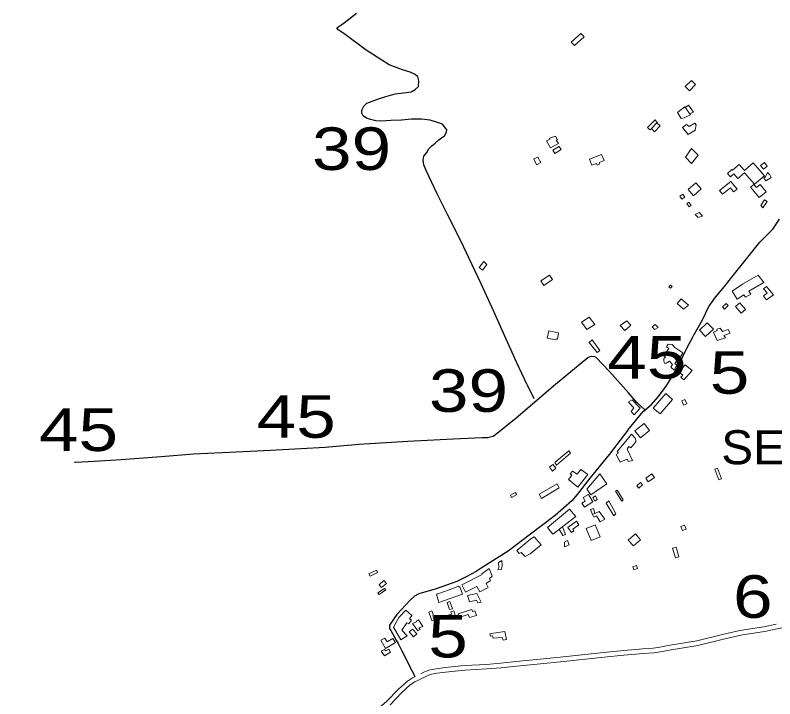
# Model space of a CAD drawing. Extents: x 476989 to 498418, y 4381813 to 4416555.
# Drawn here: x 484707 to 485600, y 4384840 to 4385643 of the extents above; entities that cross this region are included whole.
import ezdxf
from ezdxf.enums import TextEntityAlignment as Align

# ---------------------------------------------------------------- set-up
doc = ezdxf.new("R2010")
doc.units = 0
doc.header["$LTSCALE"] = 20
doc.linetypes.add('MEDIUM_DASHED', pattern=[4.5, 3, -1.5])
for name, color, linetype, lineweight in [('13', 7, 'Continuous', 13), ('36', 7, 'Continuous', 13), ('47', 7, 'Continuous', 13), ('48', 7, 'MEDIUM_DASHED', 13), ('6', 7, 'Continuous', 25)]:
    doc.layers.add(name, color=color, linetype=linetype, lineweight=lineweight)
doc.layers.add('7', color=7, linetype='Continuous')

msp = doc.modelspace()

# ---------------------------------------------------------------- linework, layer by layer
at = {"layer": '36'}
for points in [[(485422.62, 4384890.78), (485445.5, 4384892.7), (485457.67, 4384893.65), (485465.81, 4384894.8), (485475.68, 4384896.69), (485509.45, 4384902.29), (485539.74, 4384909.58), (485559.9, 4384914.32), (485587.94, 4384918.87), (485619.65, 4384925.47)], [(485422.69, 4384896.4), (485445.04, 4384898.28), (485457.06, 4384899.22), (485464.89, 4384900.34), (485474.69, 4384902.21), (485508.34, 4384907.79), (485538.44, 4384915.04), (485558.81, 4384919.82), (485586.93, 4384924.38), (485601.44, 4384927.38)], [(485147.77, 4384832.69), (485161.73, 4384847.04), (485171.53, 4384855.86), (485177.07, 4384859.62), (485182.06, 4384861.97), (485189.79, 4384866.01), (485195.1, 4384868.19), (485202.95, 4384869.58), (485213.04, 4384870.95), (485235.55, 4384873.26), (485261.75, 4384874.66), (485278.18, 4384876.14), (485300.64, 4384878.33), (485328.67, 4384881.11), (485348.27, 4384882.97), (485399.25, 4384888.59), (485422.62, 4384890.78)], [(485183.89, 4384869.09), (485187.49, 4384870.96), (485193.57, 4384873.46), (485202.11, 4384874.97), (485212.4, 4384876.37), (485235.13, 4384878.7), (485261.36, 4384880.1), (485277.67, 4384881.57), (485300.11, 4384883.76), (485328.15, 4384886.54), (485347.71, 4384888.4), (485398.68, 4384894.02), (485422.69, 4384896.4)], [(484707.31, 4384502.21), (484734.52, 4384522.99), (484765.58, 4384547.94), (484791.08, 4384567.66), (484812.71, 4384583.16), (484848.35, 4384610.12), (484888.3, 4384639.7), (484927.89, 4384667.41), (484957.41, 4384688.58), (484989.83, 4384714.56), (485027.43, 4384743.96), (485060.66, 4384769.23), (485090.09, 4384790.79), (485112.52, 4384809.73), (485128.38, 4384822.96), (485144.01, 4384836.66), (485157.94, 4384850.98), (485168.16, 4384860.16), (485174.35, 4384864.37), (485176.85, 4384865.55)]]:
    msp.add_lwpolyline(points, dxfattribs=at)
at = {"layer": '47'}
for p, q in [((485430.73, 4385278.66), (485429.6, 4385277.65)), ((485429.64, 4385279.89), (485430.73, 4385278.66)), ((485431.59, 4385150.48), (485427.01, 4385144.68))]:
    msp.add_line(p, q, dxfattribs=at)
for points in [[(485375.86, 4385617.36), (485364.42, 4385607.2), (485360.77, 4385611.28), (485372.16, 4385621.45)], [(485501.94, 4385566.31), (485494.71, 4385558.99), (485499.66, 4385554.11), (485506.89, 4385561.43)], [(485500.76, 4385525.8), (485493.57, 4385522.16), (485490.11, 4385521.53), (485485.71, 4385528.5), (485494.07, 4385535.43)], [(485461.45, 4385516.54), (485454.91, 4385509.66), (485458.68, 4385506.07), (485465.22, 4385512.95)], [(485491.39, 4385511.08), (485498.17, 4385502.8), (485506.43, 4385508.01), (485507.49, 4385514.15), (485506.17, 4385515.97), (485499.43, 4385512.02), (485496.02, 4385514.62)], [(485336.5, 4385486.96), (485331.77, 4385495.38), (485335.76, 4385497.44), (485335.29, 4385498.25), (485342.2, 4385500.73), (485344.58, 4385496.66), (485343.21, 4385496.15), (485345.76, 4385492.09)], [(485346.38, 4385488.49), (485348.86, 4385485.12), (485341.52, 4385480.52), (485338.96, 4385484.25)], [(485382.2, 4385473.84), (485385, 4385466.76), (485390.55, 4385468.79), (485391.34, 4385466.68), (485394.27, 4385468.09), (485393.65, 4385469.76), (485399.3, 4385472.35), (485396.43, 4385479.26)], [(485501.99, 4385486.17), (485494.94, 4385476.06), (485501.89, 4385468.84), (485509.91, 4385478.63)], [(485316.66, 4385474.25), (485319.79, 4385467.3), (485324.91, 4385469.72), (485321.65, 4385475.92)], [(485576.12, 4385444.28), (485564.24, 4385457.89), (485556.57, 4385451.2), (485551.89, 4385456.56), (485547.94, 4385453.11), (485544.46, 4385457.09), (485549.66, 4385461.64), (485550.29, 4385460.91), (485558.02, 4385467.59), (485564.31, 4385460.3), (485574.72, 4385469.29), (485587.69, 4385454.27)], [(485583.19, 4385466.47), (485586.58, 4385462.08), (485591.06, 4385465.53), (485587.67, 4385469.92)], [(485591.25, 4385458.17), (485589.16, 4385453.18), (485586.96, 4385451.48), (485589.53, 4385448.14), (485595.75, 4385452.26), (485594.06, 4385455.21)], [(485513.39, 4385438.88), (485504.37, 4385430.87), (485498, 4385438.05), (485507.02, 4385446.06)], [(485534.82, 4385436.85), (485548.41, 4385447.53), (485555.55, 4385438.42), (485551.49, 4385435.24), (485547.76, 4385439.99), (485538.35, 4385432.6)], [(485571.57, 4385440.75), (485581.68, 4385428.75), (485589.75, 4385435.55), (485582.63, 4385443.99), (485578.45, 4385440.47), (485575.5, 4385443.96)], [(485488.51, 4385430.38), (485490.9, 4385426.94), (485494.12, 4385429.18), (485491.73, 4385432.62)], [(485587.94, 4385426.11), (485583.51, 4385419.27), (485585.96, 4385416.4), (485590.99, 4385424.11)], [(485496.41, 4385421.49), (485499.18, 4385417.58), (485501.63, 4385419.31), (485498.86, 4385423.22)], [(485515.18, 4385406.96), (485509.98, 4385405.16), (485506.28, 4385408.67), (485511.49, 4385410.99)], [(485261.75, 4385350.07), (485256.55, 4385343.42), (485252.49, 4385346.53), (485257.99, 4385353.63)], [(485328.63, 4385325.22), (485324.86, 4385330.61), (485335.14, 4385337.31), (485338.56, 4385332.44)], [(485549.71, 4385318.83), (485561.98, 4385326.75), (485580.37, 4385337.6), (485587.23, 4385328.94), (485569.52, 4385318.84), (485571.72, 4385315.06), (485565.44, 4385311.55), (485563.46, 4385314.43), (485555.65, 4385309.29)], [(485477.4, 4385325.79), (485479.27, 4385324.15), (485477.42, 4385322.04), (485475.55, 4385323.68)], [(485590.08, 4385308.34), (485598.5, 4385314.38), (485590.16, 4385324.25), (485586.82, 4385321.45), (485590.88, 4385316.59), (485586.69, 4385312.74)], [(485498.45, 4385302.23), (485490, 4385309.55), (485485.17, 4385303.97), (485492.83, 4385297.33)], [(485542.75, 4385303.99), (485538.6, 4385300.17), (485540.85, 4385297.49), (485545.11, 4385301.63)], [(485559.04, 4385304.89), (485565.52, 4385297.05), (485560.45, 4385292.86), (485553.97, 4385300.7)], [(485379.07, 4385273.78), (485372.7, 4385282.19), (485381.81, 4385288.09), (485388.5, 4385279.35)], [(485462.96, 4385275.95), (485458.57, 4385273.46), (485455.91, 4385276.72), (485459.56, 4385279.6)], [(485520.66, 4385281.5), (485511.38, 4385272.95), (485518.48, 4385265.25), (485527.76, 4385273.8)], [(485535.88, 4385275.28), (485538.53, 4385271.26), (485545.24, 4385273.79), (485547.35, 4385269.41), (485540.18, 4385266.44), (485542.09, 4385263.63), (485532.37, 4385260.7), (485528.09, 4385270.51), (485532.09, 4385272.56), (485531.74, 4385273.91)], [(485345.88, 4385269.62), (485344.44, 4385262.34), (485343.13, 4385262.81), (485342.47, 4385261.32), (485332.59, 4385263.42), (485334.26, 4385272.11)], [(485385.42, 4385261.39), (485394.28, 4385248.91), (485391.08, 4385246.45), (485381.82, 4385258.29)], [(485491.87, 4385246.19), (485482.36, 4385252.63), (485479.41, 4385256.13), (485474.53, 4385256.42), (485472.69, 4385253.22), (485475.36, 4385251.23), (485469.68, 4385242.53), (485471.61, 4385240.93), (485470.02, 4385239.75), (485469.7, 4385238.63), (485469.68, 4385237.51), (485469.66, 4385235.93), (485469.95, 4385235.1), (485470.91, 4385233.81), (485472.33, 4385233.94), (485474.23, 4385235.19), (485476.05, 4385236.29), (485479.89, 4385232.48), (485477.67, 4385229.44), (485481.67, 4385225.85), (485484.68, 4385231.74), (485482.54, 4385233.72), (485485.91, 4385239.08), (485487.71, 4385238.75)], [(485502.9, 4385225.4), (485493.14, 4385214.36), (485489.67, 4385217.42), (485491.81, 4385219.85), (485487.35, 4385223.77), (485494.77, 4385232.21)], [(485471.75, 4385198.38), (485457.07, 4385181.29), (485465.18, 4385174.32), (485479.86, 4385191.41)], [(485494.31, 4385191.46), (485496.54, 4385186.14), (485492.79, 4385184.57), (485490.56, 4385189.89)], [(485446.33, 4385162.95), (485435.67, 4385154.43), (485442.19, 4385146.28), (485452.85, 4385154.8)], [(485341.54, 4385117.13), (485358, 4385131.01), (485359.88, 4385128.25), (485343.44, 4385114.36)], [(485335.12, 4385111.93), (485338.88, 4385107.2), (485342.55, 4385110.64), (485339.07, 4385115.06)], [(485357.51, 4385097.15), (485368.62, 4385088.17), (485380.36, 4385103.26), (485372.01, 4385109.03), (485367.56, 4385103.58), (485362.09, 4385107.01), (485359.66, 4385104.07), (485361.62, 4385102.4)], [(485379.23, 4385085.92), (485383.64, 4385079.14), (485402.54, 4385092.1), (485394.26, 4385104.11)], [(485458.4, 4385099.53), (485451.27, 4385094.65), (485448.34, 4385098.92), (485455.47, 4385103.8)], [(485532.7, 4385110.77), (485537.34, 4385098.3), (485534.08, 4385097.09), (485529.44, 4385109.56)], [(485346.7, 4385087.36), (485344.04, 4385092.2), (485323.12, 4385080.13), (485325.71, 4385075.16)], [(485444.62, 4385090.94), (485440.26, 4385087.1), (485437.78, 4385089.92), (485442.14, 4385093.76)], [(485290.74, 4385076.25), (485296.71, 4385079.76), (485295.04, 4385081.98), (485289.22, 4385078.94)], [(485376.42, 4385064.78), (485386.3, 4385071.05), (485380.99, 4385079.78), (485374.59, 4385076.18), (485377.22, 4385071.74), (485373.36, 4385069.71)], [(485386.27, 4385076.22), (485388.49, 4385071.93), (485391.18, 4385073.68), (485389.36, 4385078.3)], [(485414.69, 4385084.77), (485421.67, 4385073.34), (485420.02, 4385071.95), (485412.62, 4385083.7)], [(485401.88, 4385069.6), (485410.97, 4385054.66), (485413.3, 4385056.85), (485404.78, 4385072.14)], [(485332.83, 4385040.86), (485358.81, 4385062.46), (485366.1, 4385053.67), (485338.95, 4385033.1)], [(485400.09, 4385050.6), (485393.57, 4385059.83), (485385.55, 4385056.3), (485387.34, 4385053.1), (485390.5, 4385054.62), (485394.78, 4385047.66)], [(485356.66, 4385040.89), (485366.9, 4385048.44), (485369.63, 4385044), (485362.81, 4385039.04), (485363.91, 4385036.96), (485361.23, 4385035.02)], [(485378.19, 4385039.92), (485388.72, 4385044.18), (485394.8, 4385029.82), (485384.25, 4385025.7)], [(485489.62, 4385042.13), (485493.73, 4385043.77), (485495.65, 4385038.96), (485491.54, 4385037.32)], [(485436.15, 4385033.44), (485427.79, 4385026.2), (485433.84, 4385019.21), (485442.2, 4385026.45)], [(485317.22, 4385029.98), (485325.37, 4385020.45), (485312.51, 4385010.01), (485306.62, 4385006.83), (485301.81, 4385011.58), (485299.61, 4385010.55), (485296.92, 4385013.86), (485313.3, 4385027.75)], [(485356.54, 4385025.58), (485358.36, 4385020.59), (485352.67, 4385018.3), (485352.65, 4385023.86)], [(485483.95, 4385017.97), (485487.31, 4385006.49), (485483.24, 4385005.3), (485479.88, 4385016.78)], [(485275.35, 4384999.72), (485275.62, 4384993.72), (485274.51, 4384991.12), (485278.93, 4384991.49), (485279.63, 4384996.44), (485279.21, 4385002.07)], [(485434.27, 4384991.29), (485438.67, 4384992.73), (485437.56, 4384996.12), (485433.16, 4384994.68)], [(485131.88, 4384990.73), (485133.04, 4384987.96), (485124.38, 4384983.93), (485123.04, 4384986.67)], [(485232.24, 4384973.73), (485256.24, 4384985.71), (485255.64, 4384986.42), (485264.26, 4384992.64), (485267.98, 4384983.55), (485264.85, 4384980.92), (485265.96, 4384978.66), (485260.82, 4384975.22), (485262.98, 4384970.42), (485253.45, 4384965.37), (485249.92, 4384971.55), (485236.63, 4384965.07)], [(485134.96, 4384973.48), (485137.8, 4384970.26), (485143.62, 4384975.18), (485140.65, 4384978.64)], [(485135.13, 4384962.27), (485133.6, 4384964.2), (485141.49, 4384969.44), (485142.72, 4384967.81)], [(485202.26, 4384962.64), (485205.11, 4384952.88), (485232.87, 4384962.57), (485229.87, 4384971.23), (485228.85, 4384971.04), (485228.23, 4384972.06), (485221.76, 4384969.24), (485206.44, 4384963.71)], [(485241.19, 4384953.59), (485238.74, 4384961.16), (485249.91, 4384963.4), (485255.04, 4384953.22), (485251.01, 4384952.26), (485249.57, 4384955.39)], [(485218.26, 4384953.88), (485221.3, 4384945.37), (485217.52, 4384944.38), (485214.88, 4384952.63)], [(485166.54, 4384943.66), (485173.38, 4384937.5), (485170.74, 4384933.52), (485172.96, 4384932.16), (485170.02, 4384927.89), (485167.44, 4384928.93), (485161.73, 4384920.25), (485168.12, 4384913.52), (485160.35, 4384908.85), (485151.84, 4384923.7), (485158.04, 4384935.36)], [(485196.83, 4384931.59), (485193.55, 4384941.49), (485197.01, 4384942.93), (485198.74, 4384937.86), (485198.11, 4384937.64), (485199.61, 4384932.22)], [(485222.65, 4384942.91), (485225.26, 4384935.23), (485216.88, 4384932.94), (485215.88, 4384937.84), (485220.3, 4384938.94), (485219.08, 4384941.85)], [(485249.49, 4384937.5), (485241.12, 4384935.21), (485239.52, 4384938.69), (485228.76, 4384935.35), (485227.77, 4384939.36), (485244.05, 4384944.48), (485244.89, 4384942.19), (485247.54, 4384943.11)], [(485186.49, 4384924.62), (485181.37, 4384932.42), (485178.47, 4384930.93), (485178.71, 4384930.27), (485174.01, 4384928), (485180.62, 4384919.36), (485183.12, 4384920.9), (485181.75, 4384922.86)], [(485174.13, 4384921.38), (485179.41, 4384916.01), (485175.21, 4384912.35), (485170.29, 4384918.41)], [(485266.7, 4384916.2), (485282.71, 4384918.56), (485284.62, 4384909.24), (485280.59, 4384908.66), (485279.6, 4384911.79), (485269.14, 4384910.81), (485268.41, 4384913.55), (485265.87, 4384913.33), (485264.93, 4384915.83)], [(485142.63, 4384898.78), (485154.08, 4384905.6), (485151.02, 4384910.61), (485144.58, 4384906.61), (485141.69, 4384910.99), (485137.02, 4384908.61)], [(485137.57, 4384895.7), (485141.36, 4384889.94), (485148.18, 4384894.62), (485146.28, 4384897.8), (485142.69, 4384896.02), (485141.37, 4384897.6)]]:
    msp.add_lwpolyline(points, close=True, dxfattribs=at)
for points in [[(485429.64, 4385279.89), (485426.15, 4385283.84), (485418.4, 4385278.2), (485423.65, 4385272.41), (485429.6, 4385277.65)], [(485427.86, 4385188.7), (485432.25, 4385191), (485441.64, 4385181.18)], [(485441.64, 4385181.18), (485434.85, 4385173.17), (485431, 4385177.06), (485434.44, 4385181.58), (485427.86, 4385188.36)], [(485426.79, 4385133.81), (485428.39, 4385136.27), (485430.92, 4385134.66), (485436.72, 4385141.78), (485436.75, 4385143.51), (485435.88, 4385145.77), (485431.59, 4385150.48)], [(485427.01, 4385144.68), (485414.85, 4385130.05), (485416.09, 4385128.19), (485413.43, 4385126.89), (485418.24, 4385117.89), (485426.55, 4385121.28)], [(485426.76, 4385132.14), (485426.34, 4385133.12), (485426.79, 4385133.81)], [(485426.55, 4385121.28), (485428.06, 4385118.42), (485432.65, 4385119.55), (485426.76, 4385132.14)], [(485385.55, 4385056.3), (485383.4, 4385062.17), (485386.75, 4385063.22), (485388.34, 4385057.54)], [(485350.4, 4385041.78), (485353.89, 4385032.82), (485350.82, 4385031.71), (485346.73, 4385039)]]:
    msp.add_lwpolyline(points, dxfattribs=at)
at = {"layer": '48'}
for points in [[(485494.62, 4385534.65), (485498.59, 4385537.17), (485504.3, 4385529.07), (485499.88, 4385527.08)], [(485462.03, 4385516), (485459.32, 4385519.8), (485450.49, 4385510.99), (485453.01, 4385508.33), (485455.17, 4385509.42)]]:
    msp.add_lwpolyline(points, dxfattribs=at)
at = {"layer": '6'}
msp.add_line((485317.14, 4385192.15), (485308.96, 4385209), dxfattribs=at)
for points in [[(485085.26, 4385628.04), (485091.15, 4385632.01), (485096.05, 4385635.71), (485108.29, 4385645.35)], [(485308.74, 4385209.32), (485296.92, 4385234.62), (485284.43, 4385262.28), (485269.87, 4385294.93), (485255.01, 4385327.15), (485244.49, 4385349.47), (485230.92, 4385377.71), (485215.65, 4385407.92), (485203.16, 4385433.2), (485190.33, 4385460.5), (485187.63, 4385466.91), (485186.62, 4385472.64), (485187.63, 4385477.36), (485190.89, 4385481.57), (485193.57, 4385485.92), (485197.06, 4385489.39), (485200.8, 4385492.38), (485205.32, 4385496.6), (485208.41, 4385498.94), (485211.95, 4385501.28), (485214.31, 4385505.63), (485214.74, 4385508.31), (485209.48, 4385515.04), (485203.51, 4385516.95), (485195.07, 4385519.6), (485184.8, 4385520.86), (485173.16, 4385520.87), (485161.39, 4385519.61), (485148.88, 4385519.03), (485137.95, 4385518.42), (485131.25, 4385518.7), (485124.8, 4385520.19), (485120.08, 4385522.1), (485116.29, 4385524.57), (485114.78, 4385527.83), (485114.56, 4385531.16), (485116.92, 4385535.98), (485120.69, 4385539.39), (485134.43, 4385544.79), (485142.84, 4385547.22), (485153.81, 4385550.55), (485163.77, 4385551.71), (485172.59, 4385552.94), (485177.26, 4385555.7), (485181.21, 4385559.31), (485181.69, 4385565.62), (485180.62, 4385570.61), (485177.49, 4385573.08), (485171.64, 4385576.01), (485162.45, 4385578.88), (485146.78, 4385584.79), (485119.71, 4385602.02), (485093.36, 4385621.51), (485087.04, 4385625.83), (485085.38, 4385628.14)], [(485504.14, 4385265.76), (485509.89, 4385275.82), (485514.92, 4385285.15), (485522.59, 4385300.57), (485530.19, 4385311.59), (485540.73, 4385324.04), (485546.48, 4385331.36), (485563.74, 4385352.91), (485582.43, 4385376.13), (485597.52, 4385391.7), (485605.43, 4385403.19)], [(485427.21, 4385155.18), (485445.15, 4385177.06), (485454.85, 4385185.2), (485463.48, 4385194.77), (485472.34, 4385206.98), (485479.05, 4385217.52), (485485.93, 4385229.85), (485497.43, 4385253.31), (485504.14, 4385265.28)], [(484776.91, 4385117.64), (484778.74, 4385117.71), (484800.28, 4385118.92), (484831.98, 4385121), (484878.85, 4385124.3), (484916.93, 4385127.45), (484967.4, 4385129.79), (485007.23, 4385131.89), (485042.9, 4385133.62), (485071.57, 4385135.19), (485111.25, 4385138.74), (485168.74, 4385142.21), (485221.87, 4385145.3), (485256.19, 4385146.79), (485262.58, 4385146.84), (485265.43, 4385147.4), (485269.18, 4385148.39), (485271.82, 4385150.33), (485295.88, 4385169.82), (485342.32, 4385209.37), (485380.09, 4385240.53), (485384.25, 4385242.18), (485388.13, 4385241.7), (485389.63, 4385241.04), (485389.91, 4385240.71), (485405.62, 4385224.4), (485428.07, 4385199.13)], [(485447.21, 4385179.34), (485437.95, 4385187.81), (485428.09, 4385199.1), (485428.07, 4385199.13)], [(485427.21, 4385155.18), (485405.21, 4385126.89), (485382.59, 4385098.77), (485367.56, 4385079.71), (485361.63, 4385072.41), (485341.83, 4385055.04), (485311.5, 4385032.01), (485286.65, 4385012.95), (485254.81, 4384992.98), (485249.03, 4384989.33), (485237.16, 4384982.81), (485226.33, 4384977.63), (485202.03, 4384968.94), (485181.81, 4384963.08), (485176.45, 4384960.11), (485171.5, 4384955.6), (485155.92, 4384938.89), (485147.88, 4384927.31), (485147.13, 4384926), (485147.27, 4384922.29), (485148.81, 4384919.8), (485155.15, 4384908.42), (485157.31, 4384904.48), (485161.8, 4384896.09), (485168.3, 4384883.05), (485171.89, 4384875.57), (485174.86, 4384870), (485176.85, 4384865.55)]]:
    msp.add_lwpolyline(points, dxfattribs=at)

# ---------------------------------------------------------------- texts
at = {"layer": '13', "width": 1.25}
for s, p in [('39', (485102.6, 4385461.1)), ('45', (485449.56, 4385216)), ('5', (485546.77, 4385198.14)), ('39', (485239.97, 4385176.84)), ('45', (485037.56, 4385146.41)), ('45', (484781.71, 4385130.81)), ('6', (485574.19, 4384934.8)), ('5', (485215.97, 4384888.23))]:
    msp.add_text(s, height=50, dxfattribs=at).set_placement(p, align=Align.CENTER)
at = {"layer": '7', "width": 1.05}
msp.add_text('SES OLLERIES', height=40, dxfattribs=at).set_placement((485738.4, 4385115.23), align=Align.CENTER)

doc.saveas('drawing.dxf')
